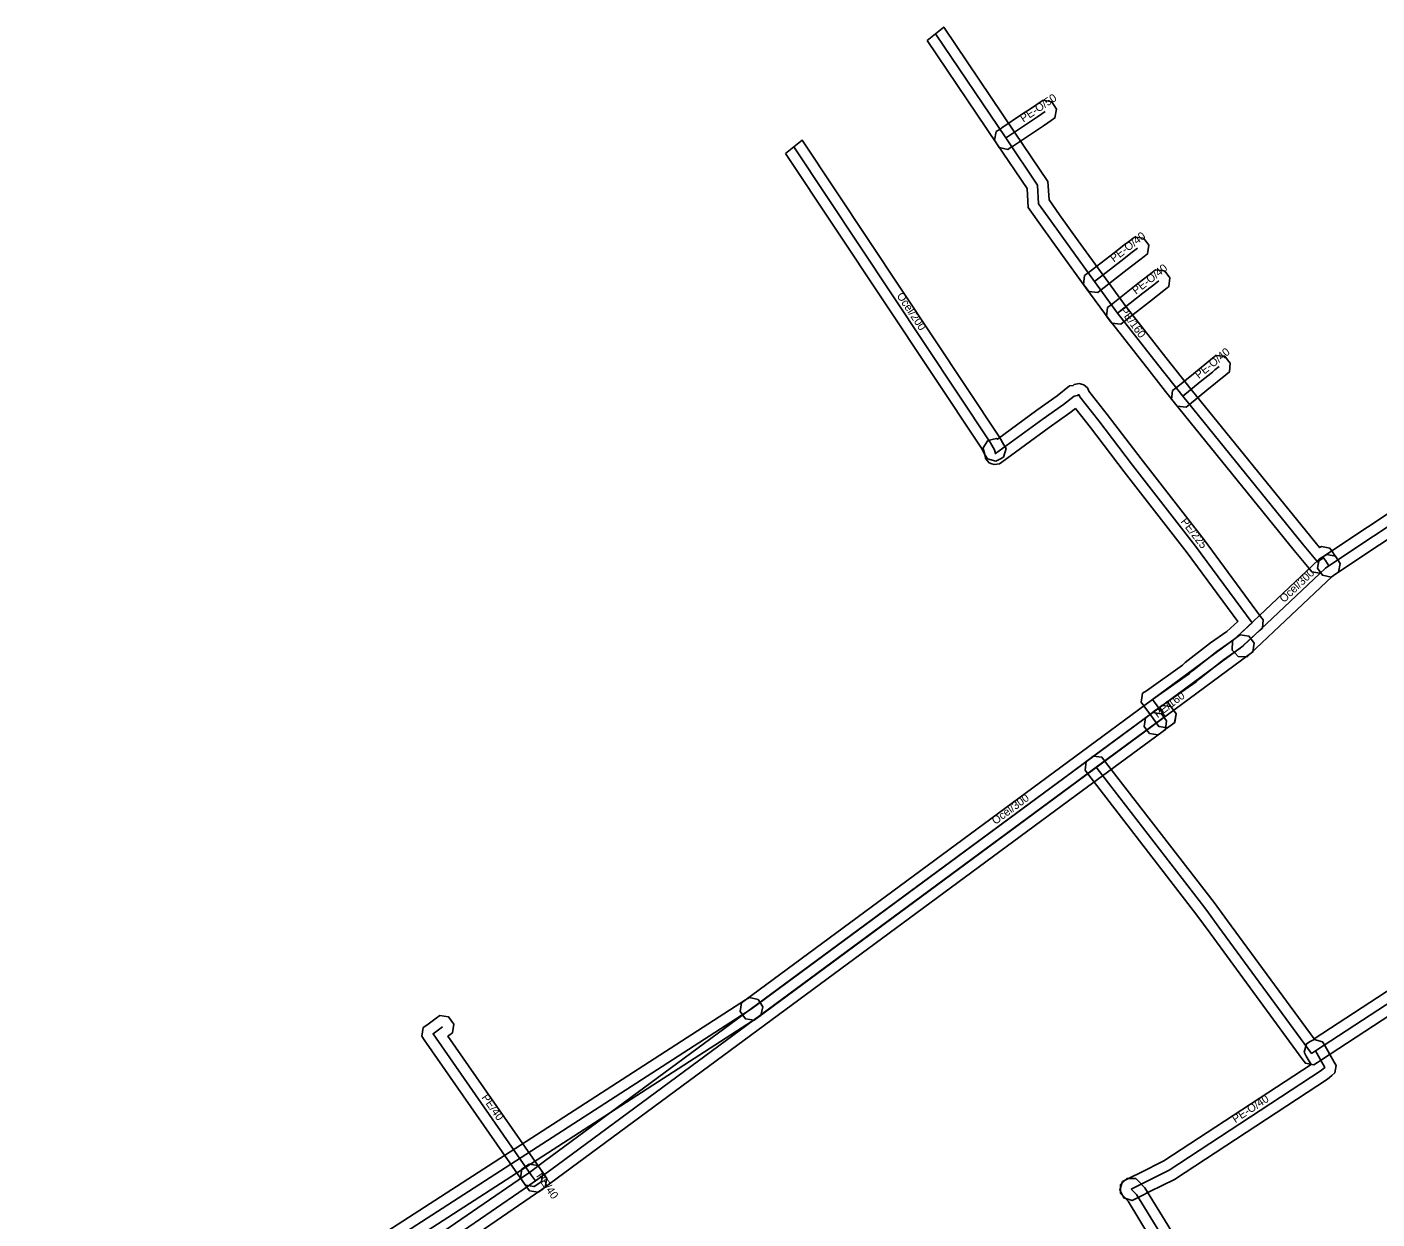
# Model space of a CAD drawing. Extents: x -492768 to -492424, y -1126490 to -1126252.
# Drawn here: x -492687.3 to -492560.8, y -1126376.7 to -1126265 of the extents above; entities that cross this region are included whole.
import ezdxf

# ---------------------------------------------------------------- set-up
doc = ezdxf.new("R2010")
doc.units = 0
for name, color, linetype in [('1', 7, 'Continuous'), ('14', 7, 'Continuous'), ('20', 7, 'Continuous'), ('24', 7, 'Continuous'), ('30', 7, 'Continuous')]:
    doc.layers.add(name, color=color, linetype=linetype)

msp = doc.modelspace()

# ---------------------------------------------------------------- linework, layer by layer
at = {"layer": '1'}
for points in [[(-492602.98, -1126266.21), (-492601.41, -1126264.96), (-492594.77, -1126274.8), (-492591.65, -1126279.44), (-492591.55, -1126281.17), (-492590.56, -1126282.55), (-492588.81, -1126284.99), (-492586.47, -1126288.21), (-492584.32, -1126291.17), (-492580.59, -1126295.93), (-492579.04, -1126297.89), (-492578.24, -1126298.93), (-492567.02, -1126312.75), (-492566.2, -1126313.75), (-492566.03, -1126313.64), (-492565.22, -1126313.8), (-492564.99, -1126314.14), (-492564.82, -1126314.39), (-492564.49, -1126314.89), (-492564.26, -1126315.24), (-492564.42, -1126316.05), (-492564.77, -1126316.28), (-492565.12, -1126316.51), (-492565.93, -1126316.34), (-492566.1, -1126316.08), (-492566.17, -1126316.13), (-492566.93, -1126316.01), (-492567.17, -1126315.71), (-492568.57, -1126314.01), (-492579.8, -1126300.17), (-492580.62, -1126299.13), (-492582.16, -1126297.16), (-492585.92, -1126292.37), (-492588.09, -1126289.39), (-492590.43, -1126286.16), (-492592.18, -1126283.72), (-492593.51, -1126281.87), (-492593.61, -1126280.1), (-492596.43, -1126275.92)], [(-492596.49, -1126274.75), (-492596.14, -1126274.52), (-492595.98, -1126274.42), (-492594.13, -1126273.17), (-492593.2, -1126272.55), (-492592.79, -1126272.27), (-492592.46, -1126272.05), (-492592.11, -1126271.82), (-492591.3, -1126271.98), (-492591.07, -1126272.32), (-492590.84, -1126272.67), (-492591, -1126273.48), (-492591.35, -1126273.71), (-492591.67, -1126273.93), (-492592.08, -1126274.21), (-492593.01, -1126274.83), (-492594.88, -1126276.08), (-492595.06, -1126276.2), (-492595.41, -1126276.43), (-492596.22, -1126276.25), (-492596.44, -1126275.9), (-492596.67, -1126275.55)], [(-492616.24, -1126276.82), (-492614.67, -1126275.57), (-492596.18, -1126303.4), (-492595.78, -1126304.1), (-492595.58, -1126304.46), (-492595.8, -1126305.26), (-492596.16, -1126305.46), (-492596.52, -1126305.66), (-492597.32, -1126305.44), (-492597.52, -1126305.08), (-492597.88, -1126304.44)], [(-492588.22, -1126288.26), (-492587.89, -1126288.01), (-492585.45, -1126286.11), (-492584.37, -1126285.28), (-492584.24, -1126285.18), (-492583.86, -1126284.89), (-492583.53, -1126284.64), (-492582.71, -1126284.74), (-492582.46, -1126285.07), (-492582.21, -1126285.4), (-492582.31, -1126286.22), (-492582.64, -1126286.47), (-492583.04, -1126286.78), (-492583.15, -1126286.86), (-492584.22, -1126287.69), (-492586.67, -1126289.59), (-492586.99, -1126289.84), (-492587.82, -1126289.74), (-492588.07, -1126289.41), (-492588.32, -1126289.09)], [(-492586.06, -1126291.24), (-492585.74, -1126290.98), (-492583.37, -1126289.13), (-492581.89, -1126287.96), (-492581.56, -1126287.71), (-492580.74, -1126287.81), (-492580.48, -1126288.13), (-492580.23, -1126288.46), (-492580.33, -1126289.28), (-492580.65, -1126289.54), (-492582.14, -1126290.7), (-492584.5, -1126292.56), (-492584.83, -1126292.81), (-492585.65, -1126292.71), (-492585.91, -1126292.39), (-492586.16, -1126292.06)], [(-492579.97, -1126299.03), (-492579.65, -1126298.77), (-492578.02, -1126297.45), (-492576.23, -1126295.99), (-492575.91, -1126295.73), (-492575.09, -1126295.82), (-492574.82, -1126296.14), (-492574.56, -1126296.46), (-492574.65, -1126297.28), (-492574.97, -1126297.55), (-492576.75, -1126299), (-492578.39, -1126300.33), (-492578.71, -1126300.59), (-492579.54, -1126300.5), (-492579.8, -1126300.18), (-492580.06, -1126299.86)], [(-492596.47, -1126303.52), (-492596.39, -1126303.57), (-492592.7, -1126300.87), (-492590.8, -1126299.52), (-492589.62, -1126298.6), (-492589.29, -1126298.54), (-492589.18, -1126298.46), (-492588.73, -1126298.38), (-492588.52, -1126298.43), (-492588.3, -1126298.49), (-492587.95, -1126298.78), (-492587.86, -1126298.99), (-492587.81, -1126299.09), (-492586.09, -1126301.27), (-492582.93, -1126305.42), (-492577.01, -1126313.02), (-492571.72, -1126320.21), (-492571.49, -1126320.52), (-492571.56, -1126321.28), (-492571.85, -1126321.54), (-492573.64, -1126323.16), (-492575.21, -1126324.27), (-492577.46, -1126326.04), (-492577.75, -1126326.31), (-492580.46, -1126328.21), (-492580.18, -1126328.59), (-492579.89, -1126328.99), (-492579.65, -1126329.33), (-492579.78, -1126330.15), (-492580.11, -1126330.39), (-492580.45, -1126330.63), (-492581.27, -1126330.5), (-492581.51, -1126330.17), (-492581.8, -1126329.77), (-492582.67, -1126328.57), (-492582.92, -1126328.23), (-492582.85, -1126327.81), (-492582.78, -1126327.4), (-492582.43, -1126327.16), (-492579.03, -1126324.77), (-492578.78, -1126324.52), (-492576.41, -1126322.67), (-492574.9, -1126321.6), (-492573.86, -1126320.66), (-492578.61, -1126314.22), (-492584.51, -1126306.64), (-492587.67, -1126302.49), (-492589.08, -1126300.71), (-492589.6, -1126301.12), (-492591.53, -1126302.49), (-492595.98, -1126305.75), (-492596.18, -1126305.9), (-492596.68, -1126305.97), (-492596.92, -1126305.88), (-492597.16, -1126305.79), (-492597.49, -1126305.41), (-492597.54, -1126305.16), (-492597.62, -1126304.81), (-492597.72, -1126304.41), (-492597.28, -1126303.71), (-492596.87, -1126303.61)], [(-492540.65, -1126329.1), (-492556.74, -1126310.94), (-492560.59, -1126313.5), (-492564.77, -1126316.28), (-492565.11, -1126316.51), (-492565.93, -1126316.34), (-492566.16, -1126316), (-492566.38, -1126315.66), (-492566.22, -1126314.84), (-492565.88, -1126314.61), (-492561.7, -1126311.83), (-492557.13, -1126308.79), (-492556.82, -1126308.59), (-492556.07, -1126308.68), (-492555.83, -1126308.96), (-492555.26, -1126309.6), (-492539.15, -1126327.77), (-492538.88, -1126328.08), (-492538.93, -1126328.91), (-492539.24, -1126329.18), (-492539.55, -1126329.46), (-492540.37, -1126329.41)], [(-492574.36, -1126322.52), (-492574.06, -1126322.24), (-492566.27, -1126314.87), (-492565.88, -1126314.61), (-492565.53, -1126314.38), (-492564.72, -1126314.55), (-492564.49, -1126314.89), (-492564.26, -1126315.24), (-492564.42, -1126316.05), (-492564.77, -1126316.28), (-492565.02, -1126316.44), (-492572.69, -1126323.69), (-492572.99, -1126323.98), (-492573.82, -1126323.95), (-492574.1, -1126323.65), (-492574.39, -1126323.35)], [(-492620.36, -1126356.41), (-492620.03, -1126356.16), (-492573.97, -1126322.16), (-492573.64, -1126321.91), (-492572.82, -1126322.04), (-492572.57, -1126322.37), (-492572.32, -1126322.7), (-492572.45, -1126323.52), (-492572.78, -1126323.77), (-492618.84, -1126357.77), (-492619.18, -1126358.02), (-492620, -1126357.9), (-492620.24, -1126357.56), (-492620.49, -1126357.23)], [(-492579.77, -1126330.13), (-492580.1, -1126330.38), (-492580.5, -1126330.68), (-492580.98, -1126331.04), (-492581.31, -1126331.29), (-492582.13, -1126331.17), (-492582.38, -1126330.84), (-492582.63, -1126330.51), (-492582.51, -1126329.69), (-492582.18, -1126329.44), (-492581.7, -1126329.08), (-492581.3, -1126328.78), (-492580.97, -1126328.53), (-492580.15, -1126328.65), (-492579.9, -1126328.98), (-492579.65, -1126329.31)], [(-492640.61, -1126373.48), (-492640.85, -1126373.14), (-492650.09, -1126359.87), (-492650.32, -1126359.54), (-492650.19, -1126358.73), (-492649.86, -1126358.49), (-492648.97, -1126357.84), (-492648.64, -1126357.6), (-492647.82, -1126357.73), (-492647.57, -1126358.06), (-492647.33, -1126358.4), (-492647.46, -1126359.21), (-492647.79, -1126359.46), (-492647.89, -1126359.53), (-492639.21, -1126372), (-492638.97, -1126372.34), (-492639.12, -1126373.15), (-492639.46, -1126373.39), (-492639.8, -1126373.63)], [(-492580.78, -1126371.21), (-492567, -1126362.18), (-492567.45, -1126361.4), (-492567.65, -1126361.04), (-492567.43, -1126360.24), (-492567.07, -1126360.03), (-492566.71, -1126359.83), (-492565.91, -1126360.05), (-492565.7, -1126360.41), (-492564.83, -1126361.96), (-492564.65, -1126362.27), (-492564.78, -1126362.98), (-492565.05, -1126363.21), (-492565.45, -1126363.55), (-492579.78, -1126372.95), (-492582.1, -1126374.1), (-492582.95, -1126374.53), (-492583.39, -1126374.75), (-492583.76, -1126374.94), (-492584.55, -1126374.68), (-492584.73, -1126374.31), (-492584.92, -1126373.94), (-492584.66, -1126373.15), (-492584.29, -1126372.97), (-492583.85, -1126372.75), (-492583, -1126372.32)], [(-492640.24, -1126374.01), (-492640.48, -1126373.67), (-492640.85, -1126373.14), (-492641.09, -1126372.8), (-492640.94, -1126371.98), (-492640.6, -1126371.75), (-492640.26, -1126371.51), (-492639.44, -1126371.66), (-492639.21, -1126372), (-492638.84, -1126372.53), (-492638.6, -1126372.87), (-492638.75, -1126373.69), (-492639.09, -1126373.92), (-492639.43, -1126374.16)], [(-492577.3, -1126386.19), (-492577.51, -1126385.84), (-492582.12, -1126378.29), (-492584.14, -1126374.98), (-492584.55, -1126374.56), (-492584.84, -1126374.27), (-492584.84, -1126373.44), (-492584.54, -1126373.15), (-492584.25, -1126372.86), (-492583.42, -1126372.86), (-492583.13, -1126373.16), (-492582.56, -1126373.74), (-492580.41, -1126377.25), (-492575.81, -1126384.79), (-492575.59, -1126385.15), (-492575.79, -1126385.95), (-492576.14, -1126386.17), (-492576.49, -1126386.39)]]:
    msp.add_lwpolyline(points, close=True, dxfattribs=at)
for points in [[(-492672.24, -1126394.25), (-492641.3, -1126373.02), (-492640.24, -1126372.29), (-492638.82, -1126371.24), (-492589.58, -1126334.9), (-492587.72, -1126333.53), (-492582.17, -1126329.44), (-492581.84, -1126329.19), (-492581.02, -1126329.31), (-492580.78, -1126329.65), (-492580.53, -1126329.98), (-492580.65, -1126330.8), (-492580.99, -1126331.04), (-492586.54, -1126335.14), (-492588.4, -1126336.51), (-492637.63, -1126372.85), (-492639.08, -1126373.91), (-492640.16, -1126374.66), (-492671.11, -1126395.9)], [(-492552.92, -1126353.18), (-492566.03, -1126361.74), (-492566.4, -1126361.99), (-492566.74, -1126362.21), (-492567.52, -1126362.06), (-492567.76, -1126361.74), (-492576.46, -1126349.89), (-492577.69, -1126348.2), (-492586.77, -1126336.44), (-492587.92, -1126334.94), (-492588.17, -1126334.61), (-492588.07, -1126333.79), (-492587.74, -1126333.54), (-492587.41, -1126333.28), (-492586.59, -1126333.39), (-492586.34, -1126333.72), (-492585.18, -1126335.22), (-492576.09, -1126347), (-492574.84, -1126348.71), (-492566.7, -1126359.79), (-492554.02, -1126351.5)], [(-492665.59, -1126385.57), (-492619.98, -1126356.13), (-492619.63, -1126355.9), (-492618.82, -1126356.08), (-492618.6, -1126356.43), (-492618.37, -1126356.78), (-492618.55, -1126357.58), (-492618.9, -1126357.81), (-492664.52, -1126387.26)]]:
    msp.add_lwpolyline(points, dxfattribs=at)
at = {"layer": '14'}
for points in [[(-492565.32, -1126315.45), (-492565.65, -1126314.95), (-492565.82, -1126314.7), (-492566.4, -1126315.08), (-492567.79, -1126313.38), (-492579.02, -1126299.55), (-492579.83, -1126298.51), (-492581.37, -1126296.54), (-492585.12, -1126291.77), (-492587.28, -1126288.8), (-492589.62, -1126285.57), (-492591.37, -1126283.13), (-492592.53, -1126281.52), (-492592.63, -1126279.77), (-492595.6, -1126275.36), (-492602.2, -1126265.59)], [(-492595.6, -1126275.36), (-492595.43, -1126275.25), (-492593.57, -1126274), (-492592.64, -1126273.38), (-492592.23, -1126273.1), (-492591.9, -1126272.88)], [(-492587.28, -1126288.8), (-492584.83, -1126286.9), (-492583.76, -1126286.07), (-492583.64, -1126285.98), (-492583.25, -1126285.68)], [(-492585.12, -1126291.77), (-492582.75, -1126289.91), (-492581.73, -1126289.11), (-492581.57, -1126288.99), (-492581.27, -1126288.75)], [(-492579.02, -1126299.55), (-492577.39, -1126298.22), (-492576.24, -1126297.29), (-492576.01, -1126297.1), (-492575.6, -1126296.77)], [(-492539.9, -1126328.44), (-492556.01, -1126310.27), (-492556.57, -1126309.63), (-492561.14, -1126312.67), (-492565.32, -1126315.45)], [(-492573.37, -1126322.96), (-492565.64, -1126315.66), (-492565.32, -1126315.45)], [(-492619.44, -1126356.97), (-492573.37, -1126322.96)], [(-492619.44, -1126356.97), (-492665.05, -1126386.42), (-492667.08, -1126387.7), (-492684.85, -1126398.94), (-492685.99, -1126407.76), (-492684.32, -1126408.43), (-492680.82, -1126413.09), (-492680.43, -1126413.44)]]:
    msp.add_lwpolyline(points, dxfattribs=at)
at = {"layer": '24'}
for points in [[(-492596.65, -1126304.59), (-492597.03, -1126303.92), (-492615.46, -1126276.19)], [(-492580.7, -1126329.58), (-492580.99, -1126329.18), (-492581.86, -1126327.98), (-492578.39, -1126325.54), (-492578.12, -1126325.28), (-492575.81, -1126323.47), (-492574.27, -1126322.38), (-492572.52, -1126320.8), (-492577.81, -1126313.62), (-492583.72, -1126306.03), (-492586.88, -1126301.88), (-492588.67, -1126299.62), (-492588.77, -1126299.4), (-492588.88, -1126299.48), (-492589.2, -1126299.54), (-492590.2, -1126300.32), (-492592.11, -1126301.68), (-492596.57, -1126304.94), (-492596.65, -1126304.59)], [(-492580.7, -1126329.58), (-492581.1, -1126329.88), (-492581.58, -1126330.24)], [(-492732.61, -1126466.25), (-492732.22, -1126465.79), (-492695.7, -1126414.32), (-492692.45, -1126409.74), (-492690.04, -1126408.01), (-492681.32, -1126401.7), (-492680.06, -1126400.83), (-492673.97, -1126396.65), (-492671.67, -1126395.07), (-492640.73, -1126373.84), (-492639.66, -1126373.1), (-492638.23, -1126372.04), (-492588.99, -1126335.7), (-492587.13, -1126334.33), (-492581.58, -1126330.24)], [(-492587.13, -1126334.33), (-492585.98, -1126335.83), (-492576.96, -1126347.51), (-492576.89, -1126347.6), (-492576.77, -1126347.76), (-492575.65, -1126349.3), (-492566.95, -1126361.15), (-492566.57, -1126360.9), (-492553.47, -1126352.34)], [(-492640.03, -1126372.57), (-492649.27, -1126359.3), (-492648.38, -1126358.65)], [(-492583.84, -1126373.86), (-492583.4, -1126373.64), (-492582.55, -1126373.21), (-492580.28, -1126372.08), (-492566.05, -1126362.75), (-492565.7, -1126362.45), (-492566.57, -1126360.9)], [(-492639.66, -1126373.1), (-492640.03, -1126372.57)], [(-492576.66, -1126385.31), (-492581.27, -1126377.77), (-492583.35, -1126374.36), (-492583.84, -1126373.86)]]:
    msp.add_lwpolyline(points, dxfattribs=at)

# ---------------------------------------------------------------- texts
at = {"layer": '20'}
for s, rotation, p in [('PE-O/50', 33.8248, (-492593.95, -1126273.92)), ('PE-O/40', 37.7954, (-492585.47, -1126287.04)), ('PE-O/40', 38.1155, (-492583.4, -1126290.06)), ('PE/160', 306.0274, (-492584.96, -1126291.52)), ('PE-O/40', 39.1222, (-492577.51, -1126297.96)), ('Ocel/300', 43.3699, (-492569.53, -1126318.95)), ('Ocel/300', 36.4358, (-492596.57, -1126339.74))]:
    msp.add_text(s, height=0.75, rotation=rotation, dxfattribs=at).set_placement(p)
at = {"layer": '30'}
for s, rotation, p in [('Ocel/200', 303.6062, (-492605.86, -1126290.14)), ('PE/225', 307.9063, (-492579.25, -1126311.32)), ('PE/160', 36.8699, (-492581.38, -1126329.74)), ('PE/40', 304.8547, (-492644.76, -1126365.28)), ('PE-O/40', 33.2511, (-492574.09, -1126367.69)), ('PE/40', 304.796, (-492639.64, -1126372.63))]:
    msp.add_text(s, height=0.75, rotation=rotation, dxfattribs=at).set_placement(p)

doc.saveas('drawing.dxf')
